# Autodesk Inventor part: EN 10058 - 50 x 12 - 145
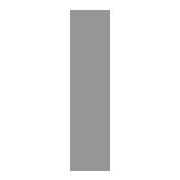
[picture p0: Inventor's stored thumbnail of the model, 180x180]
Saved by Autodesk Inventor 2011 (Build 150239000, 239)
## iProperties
IsCustomPart: 1
_CCFamilyMember: 60
_CCFamilyDisplayName: DIN EN 10058 - Hot rolled flat steel bars for general purposes
_FrameMemberDoc: Frame Member File
_Version: 15.0.0
_GetPNFromCC: 1
Created: 2010-02
Part Number: EN 10058 - 50 x 12 - 145
Material: Steel, Mild
Description: flat steel bar
Document SubType Name: Modeling
Standard: DIN
Designer: PC
Standard Revision: 2004
Standards Organization: DIN
Language: en-US
Size Designation: 50 x 12
Categories: <MemberInstance><Categories><Category DisplayName="Structural Shapes" InternalName="089c4875-fa83-4c05-b084-43b9cc11f5ed" Mnemonic="GRDR"><CategoryParameter Dis
Stock Number: 50 x 12
Density: 7.86 g/cm^3
G_L: 145.000 mm
G_W: 12.000 mm
G_H: 50.000 mm
Author: PC
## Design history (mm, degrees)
node "Start plane"
node "End plane"
sketch "Sketch"
  geometry: L1 (6, -25)-(-6, -25); L2 (-6, -25)-(-6, 25); L3 (-6, 25)-(6, 25); L4 (6, 25)-(6, -25); L5 (-6, 0)-(8, 0); L6 (0, -30)-(0, 40); L7 (0, 54)-(0, -44) reference; L8 (-9.2, 0)-(13.2, 0) reference
  constraints: 12 end point, 2 collinear, 2 parallel, 1 horizontal, 1 perpendicular
  dimensions: "d0" = 50 distance between parallel lines of L3 L1 (= G_W); "d1" = 12 distance between parallel lines of L4 L2 (= G_H); "d4" = 6 distance between parallel lines of L6 L4 (= 0.5 x d1); "d5" = 25 distance between parallel lines of L5 L3 (= 0.5 x d0)
extrude "Body" new body sketch "Sketch" stored distance "d2" = 145 (= G_L); taper "d3" = 0 deg
node "Driven Length"
  sketch "Sketch3"
    geometry: L1 (0, 0)-(10, 0) reference
    constraints: 2 end point, 1 horizontal
  workplane "Work Plane3"
  sketch "Sketch4"
    geometry: L1 (-2, 0)-(12, 0) reference; L2 (-2, 145)-(12, 145) reference
    dimensions: "d9" = 145 distance between parallel lines of L1 L2 (derived)
body "Solid1"
other parameters: "G_W" = 50 [user parameter; used in 1 equation term], "G_H" = 12 [user parameter; used in 1 equation term], "G_L" = 145 (= d9) [user parameter; used in 1 equation term], "G_OFFSET_START" = 0 [user parameter; used in 1 equation term], "G_OFFSET_END" = 0 [user parameter; used in 1 equation term], "d6" = 0 (computed from G_OFFSET_START), "d7" = 145 (= G_OFFSET_END + B_L), "B_L" = 145 [user parameter; used in 1 equation term], "d8" = 90 deg, "MAS" = 0.471 [user parameter]
